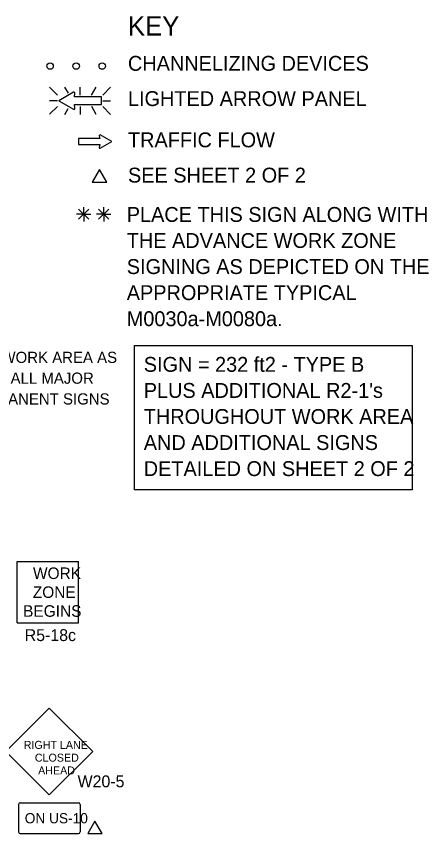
# Model space of a CAD drawing. Extents: x 16722 to 18475, y 7001 to 8243.
# Drawn here: x 17171 to 17429, y 7698 to 8209 of the extents above; entities that cross this region are included whole.
import ezdxf

# ---------------------------------------------------------------- set-up
doc = ezdxf.new("R2010")
doc.units = 0
for name, color, linetype in [('MT_SCRATCH_LEVEL_E', 7, 'Continuous'), ('TRAFFIC_SIGNS_PR', 7, 'Continuous'), ('TYPICAL_TEXT_DIMEN_EX', 7, 'Continuous'), ('TYPICAL_TEXT_DIMEN_PR', 7, 'Continuous')]:
    doc.layers.add(name, color=color, linetype=linetype)

msp = doc.modelspace()

# ---------------------------------------------------------------- linework, layer by layer
at = {"layer": 'MT_SCRATCH_LEVEL_E'}
for p, q in [((17223.51, 8132.64), (17210.25, 8132.64)), ((17210.25, 8132.64), (17210.25, 8128.9)), ((17223.19, 8134.41), (17223.51, 8132.64)), ((17231.12, 8130.79), (17223.88, 8134.9)), ((17210.25, 8128.9), (17223.51, 8128.9)), ((17223.51, 8128.9), (17223.19, 8127.12)), ((17223.88, 8126.64), (17231.12, 8130.79))]:
    msp.add_line(p, q, dxfattribs=at)
for centre, start, end in [((17223.65, 8134.49), 60.4248, 189.9638), ((17223.65, 8127.05), 170.0362, 299.7731)]:
    msp.add_arc(centre, 0.463, start, end, dxfattribs=at)
at = {"layer": 'TRAFFIC_SIGNS_PR'}
for p, q in [((17192.18, 8164.79), (17197.12, 8159.86)), ((17203.94, 8160.97), (17201.74, 8164.8)), ((17211.26, 8159.86), (17211.26, 8164.8)), ((17218.5, 8159.86), (17221.35, 8164.8)), ((17225.41, 8159.86), (17230.35, 8164.8)), ((17197.12, 8156.3), (17192.18, 8156.3)), ((17192.18, 8147.82), (17197.12, 8152.75)), ((17211.26, 8152.75), (17211.26, 8147.81)), ((17221.39, 8147.81), (17218.54, 8152.75)), ((17225.41, 8156.3), (17230.35, 8156.3)), ((17225.41, 8152.75), (17230.35, 8147.81)), ((17201.69, 8147.81), (17203.81, 8151.48)), ((17171.82, 7829.84), (17171.82, 7868.24)), ((17171.82, 7868.24), (17210.22, 7868.24)), ((17210.22, 7829.84), (17210.22, 7868.24)), ((17171.82, 7829.84), (17210.22, 7829.84)), ((17192.02, 7776.52), (17164.87, 7749.37)), ((17219.17, 7749.37), (17192.02, 7776.52)), ((17164.87, 7749.37), (17192.02, 7722.23)), ((17192.02, 7722.23), (17219.17, 7749.37)), ((17172.82, 7716.23), (17172.82, 7699.02)), ((17173.82, 7717.23), (17210.22, 7717.23)), ((17211.22, 7716.23), (17211.22, 7699.02)), ((17173.82, 7698.02), (17210.22, 7698.02))]:
    msp.add_line(p, q, dxfattribs=at)
for points in [[(17207.19, 8161.58), (17197.9, 8156.3), (17207.19, 8150.98)], [(17208.07, 8151.61), (17207.67, 8153.88), (17224.68, 8153.88), (17224.68, 8158.68), (17207.67, 8158.68), (17208.07, 8160.96)]]:
    msp.add_lwpolyline(points, dxfattribs=at)
for centre in [(17192.52, 8177.99), (17208.82, 8177.99), (17225.12, 8177.99)]:
    msp.add_circle(centre, 2, dxfattribs=at)
for centre, radius, start, end in [((17207.48, 8161.06), 0.598, 350.7308, 118.8916), ((17207.48, 8151.51), 0.597, 241.4833, 9.9593), ((17173.82, 7716.22), 1, 90, 180), ((17210.22, 7716.22), 1, 0, 90), ((17173.82, 7699.02), 1, 180, 270), ((17210.22, 7699.02), 1, 270, 0)]:
    msp.add_arc(centre, radius, start, end, dxfattribs=at)
at = {"layer": 'TYPICAL_TEXT_DIMEN_EX'}
for p, q in [((17210.31, 8088.57), (17216.69, 8082.2)), ((17216.69, 8088.57), (17210.31, 8082.2)), ((17213.5, 8085.39), (17213.5, 8089.84)), ((17229.24, 8088.57), (17222.86, 8082.2)), ((17222.87, 8088.57), (17229.24, 8082.2)), ((17226.05, 8085.39), (17226.05, 8089.84)), ((17213.5, 8085.39), (17208.97, 8085.39)), ((17213.5, 8085.39), (17216.69, 8085.39)), ((17213.5, 8085.39), (17217.98, 8085.39)), ((17213.5, 8085.39), (17213.5, 8080.89)), ((17226.05, 8085.39), (17221.52, 8085.39)), ((17226.05, 8085.39), (17229.24, 8085.39)), ((17226.05, 8085.39), (17230.53, 8085.39)), ((17226.05, 8085.39), (17226.05, 8080.89))]:
    msp.add_line(p, q, dxfattribs=at)
msp.add_lwpolyline([(17245.3, 8003.21), (17418.95, 8003.21), (17418.95, 7912.88), (17245.3, 7912.88)], close=True, dxfattribs=at)
at = {"layer": 'TYPICAL_TEXT_DIMEN_PR'}
for points in [[(17223.4, 8113.27), (17218.87, 8105.44), (17227.92, 8105.44)], [(17220.53, 7705.8), (17216, 7697.96), (17225.05, 7697.96)]]:
    msp.add_lwpolyline(points, close=True, dxfattribs=at)

# ---------------------------------------------------------------- texts
at = {"layer": 'TRAFFIC_SIGNS_PR'}
for s, height, p in [('PLACE THROUGHOUT WORK AREA AS', 7, (17059.11, 7992.33)), ('INDICATED AND AFTER ALL MAJOR', 7, (17059.11, 7979.33)), ('CROSSROADS IF PERMANENT SIGNS', 7, (17059.11, 7966.33)), ('WORK', 7.217, (17181.82, 7857.21)), ('ZONE', 7.217, (17181.7, 7845.4)), ('BEGINS', 7.217, (17175.63, 7833.59)), ('R5-18c', 7.44, (17176.63, 7818.4)), ('RIGHT LANE', 4.999, (17175.99, 7750.98)), ('CLOSED', 4.999, (17182.98, 7742.98)), ('AHEAD', 4.999, (17185.03, 7734.98)), ('W20-5', 7.439, (17209.7, 7726.95)), ('ON US-10', 6.401, (17176.65, 7704.42))]:
    msp.add_text(s, height=height, dxfattribs=at).set_placement(p)
at = {"layer": 'TYPICAL_TEXT_DIMEN_EX'}
for s, height, p in [('KEY', 12, (17241.19, 8197.1)), ('CHANNELIZING DEVICES', 9.3, (17241.19, 8175.05)), ('LIGHTED ARROW PANEL', 9.3, (17241.19, 8153)), ('TRAFFIC FLOW', 9.3, (17241.19, 8127.2)), ('SEE SHEET 2 OF 2', 9.3, (17241.19, 8105.15)), ('PLACE THIS SIGN ALONG WITH', 9.3, (17240.44, 8080.55)), ('THE ADVANCE WORK ZONE', 9.3, (17240.44, 8064.25)), ('SIGNING AS DEPICTED ON THE', 9.3, (17240.44, 8047.95)), ('APPROPRIATE TYPICAL', 9.3, (17240.44, 8031.65)), ('M0030a-M0080a.', 9.3, (17240.44, 8015.35)), ('SIGN = 232 ft2 - TYPE B', 9.3, (17251.07, 7986.79)), ("PLUS ADDITIONAL R2-1's", 9.3, (17251.07, 7970.49)), ('THROUGHOUT WORK AREA', 9.3, (17251.07, 7954.19)), ('AND ADDITIONAL SIGNS', 9.3, (17251.07, 7937.89)), ('DETAILED ON SHEET 2 OF 2', 9.3, (17251.07, 7921.59))]:
    msp.add_text(s, height=height, dxfattribs=at).set_placement(p)

doc.saveas('drawing.dxf')
